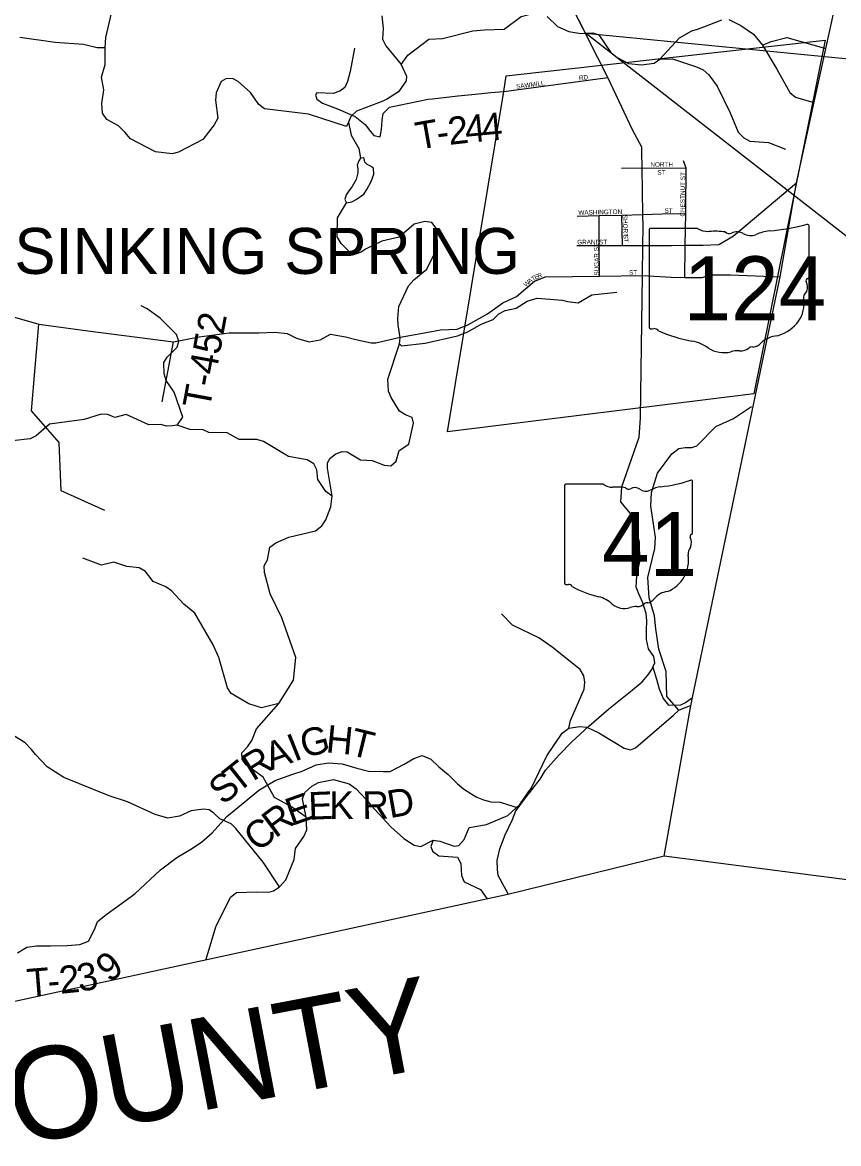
# Model space of a CAD drawing. Extents: x 0 to 34, y 0 to 22.
# Drawn here: x 5.2 to 6.881, y 14.612 to 16.923 of the extents above; entities that cross this region are included whole.
import ezdxf

# ---------------------------------------------------------------- set-up
doc = ezdxf.new("R2010")
doc.units = 0
for name, color, linetype in [('GM_X_Adjacent_County', 7, 'Continuous'), ('GM_X_Adjacent_County_Text', 7, 'Continuous'), ('GM_X_City_Street', 7, 'Continuous'), ('GM_X_City_Street_Text', 7, 'Continuous'), ('GM_X_Corporation', 7, 'Continuous'), ('GM_X_Corporation_Text', 7, 'Continuous'), ('GM_X_County', 7, 'Continuous'), ('GM_X_County_Road', 7, 'Continuous'), ('GM_X_Major_River', 7, 'Continuous'), ('GM_X_Minor_River', 7, 'Continuous'), ('GM_X_State_Location', 7, 'Continuous'), ('GM_X_State_Route', 7, 'Continuous'), ('GM_X_State_Shield', 7, 'Continuous'), ('GM_X_Township_Road', 7, 'Continuous'), ('GM_X_Township_Road_Text', 7, 'Continuous'), ('SH_Data', 7, 'Continuous')]:
    doc.layers.add(name, color=color, linetype=linetype)

msp = doc.modelspace()

# ---------------------------------------------------------------- linework, layer by layer
at = {"layer": 'GM_X_Adjacent_County'}
msp.add_lwpolyline([(9.4, 14.9965), (8.815, 15.0315), (8.2967, 15.0626), (8.1206, 15.0731), (7.1103, 15.1434), (6.9032, 15.1545), (6.5214, 15.204), (6.1992, 15.1249), (5.0219, 14.8699), (4.9843, 14.8636), (3.402, 14.5859), (3.2736, 14.5654), (2.6, 14.46)], dxfattribs=at)
at = {"layer": 'GM_X_City_Street'}
for points in [[(6.1646, 16.7778), (6.1911, 16.7802), (6.4053, 16.8091)], [(6.5648, 16.4601), (6.5648, 16.4632), (6.5658, 16.5289), (6.5659, 16.5373), (6.5666, 16.6223), (6.5609, 16.6375)], [(6.4338, 16.6218), (6.476, 16.6231), (6.5666, 16.6223)], [(6.6341, 16.4651), (6.6344, 16.4652), (6.6354, 16.4652), (6.6643, 16.4826), (6.794, 16.5922)], [(6.3424, 16.5231), (6.3872, 16.5243), (6.4342, 16.5255), (6.4778, 16.5266), (6.5172, 16.5277), (6.5172, 16.5277)], [(6.3879, 16.3996), (6.3875, 16.4627), (6.3872, 16.5243)], [(6.4355, 16.4627), (6.4342, 16.5255)], [(6.5172, 16.5277), (6.5658, 16.5289)], [(6.3415, 16.4628), (6.3875, 16.4627), (6.4355, 16.4627), (6.4778, 16.4628), (6.5368, 16.463), (6.5648, 16.4632), (6.6016, 16.4635), (6.6341, 16.4651)], [(6.5639, 16.3971), (6.5648, 16.4599), (6.5648, 16.4601)], [(6.2173, 16.3576), (6.2543, 16.3895), (6.2771, 16.3981), (6.3879, 16.3996), (6.4771, 16.4008)]]:
    msp.add_lwpolyline(points, dxfattribs=at)
at = {"layer": 'GM_X_Corporation'}
msp.add_lwpolyline([(6.075, 16.0786), (6.1911, 16.7802), (6.1959, 16.8126), (6.8533, 16.8858), (6.7061, 16.157)], close=True, dxfattribs=at)
at = {"layer": 'GM_X_County'}
msp.add_lwpolyline([(6.5214, 15.204), (6.5756, 15.5109), (6.5797, 15.5314), (6.7601, 16.3985), (6.794, 16.5922), (6.9912, 17.4939), (7.1423, 18.303), (7.4503, 19.9984), (7.5281, 20.392), (7.6111, 20.9006)], dxfattribs=at)
at = {"layer": 'GM_X_County_Road'}
msp.add_lwpolyline([(5.1486, 16.3245), (5.2333, 16.3007), (5.3343, 16.2869), (5.511, 16.264), (5.5634, 16.2747), (5.6252, 16.283), (5.6866, 16.2826), (5.7196, 16.2839), (5.745, 16.2811), (5.764, 16.2717), (5.7902, 16.2639), (5.813, 16.2686), (5.8338, 16.2797), (5.8649, 16.2746), (5.8865, 16.269), (5.9177, 16.262), (5.9275, 16.2624), (5.9775, 16.2737), (6.0203, 16.2812), (6.0608, 16.2887), (6.095, 16.29), (6.1169, 16.2993), (6.1573, 16.3219), (6.189, 16.3445), (6.2173, 16.3576)], dxfattribs=at)
at = {"layer": 'GM_X_Major_River'}
for points in [[(5.9401, 16.936), (5.9429, 16.9098), (5.9415, 16.8879), (5.9482, 16.8745), (5.98, 16.8356), (5.9904, 16.8116), (5.9899, 16.8021), (5.9741, 16.7795), (5.9498, 16.7638), (5.9384, 16.759), (5.8879, 16.7394), (5.876, 16.7286), (5.8714, 16.7169), (5.8764, 16.6903), (5.8928, 16.6628), (5.8958, 16.6428)], [(5.8958, 16.6428), (5.8923, 16.6372), (5.8891, 16.6285), (5.8905, 16.6205), (5.8907, 16.6126), (5.8871, 16.599), (5.8789, 16.5843), (5.8719, 16.5757), (5.8661, 16.5675), (5.8636, 16.5577), (5.867, 16.551)], [(5.9051, 16.6343), (5.9035, 16.6423), (5.9011, 16.6432), (5.8958, 16.6428)], [(5.867, 16.551), (5.8779, 16.5525), (5.8867, 16.5573), (5.9028, 16.5687), (5.9087, 16.5785), (5.9177, 16.595), (5.9236, 16.6101), (5.9227, 16.6223), (5.9164, 16.6262), (5.9096, 16.6297), (5.9051, 16.6343)], [(5.7841, 15.2844), (5.7539, 15.3061), (5.7185, 15.3254), (5.6955, 15.3669), (5.6613, 15.3915), (5.6519, 15.4033), (5.6517, 15.417), (5.6631, 15.4294), (5.6724, 15.4429), (5.682, 15.4667), (5.728, 15.5189), (5.7579, 15.5671), (5.7629, 15.6133), (5.7342, 15.6954), (5.7101, 15.7446), (5.6981, 15.789), (5.6974, 15.8027), (5.7044, 15.8151), (5.7092, 15.8408), (5.7214, 15.8498), (5.748, 15.8616), (5.8029, 15.8744), (5.8163, 15.8852), (5.8247, 15.8973), (5.8348, 15.9244), (5.8373, 15.9464), (5.8281, 16.0037), (5.8282, 16.0147), (5.8332, 16.0245), (5.845, 16.0335), (5.8583, 16.0379), (5.8685, 16.0378), (5.8959, 16.0212), (5.9092, 16.02), (5.9198, 16.0198), (5.945, 16.0101), (5.9586, 16.0089), (5.9693, 16.0182), (5.9756, 16.0401), (5.9954, 16.0536), (6.0053, 16.0967), (6.002, 16.1085), (5.9888, 16.1135), (5.9764, 16.1216), (5.9589, 16.1498), (5.9533, 16.1628), (5.9524, 16.1874), (5.9762, 16.2599), (5.9775, 16.2728), (5.9736, 16.2993), (5.9726, 16.3122), (5.9747, 16.3372), (5.9948, 16.3795), (6.0055, 16.3923), (6.0326, 16.414), (6.0508, 16.4517), (6.0521, 16.4759), (6.0516, 16.4983), (6.0426, 16.5101), (6.0283, 16.5125), (6.0066, 16.5067), (5.9754, 16.4797), (5.9397, 16.4714), (5.9078, 16.4561), (5.8971, 16.4487), (5.8876, 16.4453), (5.8752, 16.4477), (5.8564, 16.4669), (5.8479, 16.4806), (5.8486, 16.52), (5.867, 16.551)], [(5.5779, 14.9919), (5.5982, 15.0585), (5.6281, 15.1195), (5.6404, 15.1296), (5.6821, 15.1306), (5.7074, 15.1303), (5.717, 15.1328), (5.7292, 15.141), (5.7422, 15.1552), (5.7595, 15.1975), (5.7617, 15.2202), (5.7794, 15.245), (5.7853, 15.2582), (5.7841, 15.2844)]]:
    msp.add_lwpolyline(points, dxfattribs=at)
at = {"layer": 'GM_X_Minor_River'}
for points in [[(5.98, 16.8356), (5.9931, 16.8548), (6.0369, 16.8877), (6.0645, 16.8893), (6.1275, 16.905), (6.1513, 16.9074), (6.1915, 16.9089), (6.2269, 16.9347), (6.2508, 16.9409), (6.2858, 16.9629), (6.309, 16.9725), (6.3319, 16.9901), (6.3544, 17.0138), (6.4018, 17.0243), (6.4383, 17.0395), (6.46, 17.0529), (6.4964, 17.0578), (6.507, 17.0642), (6.5207, 17.0724), (6.5302, 17.078), (6.573, 17.1219), (6.593, 17.146), (6.6179, 17.1844), (6.6305, 17.196)], [(5.8714, 16.7169), (5.8671, 16.7078), (5.7891, 16.7336), (5.698, 16.7444), (5.6864, 16.7536), (5.6692, 16.7784), (5.6437, 16.8006), (5.632, 16.8068), (5.6184, 16.8062), (5.6089, 16.8006), (5.5984, 16.7772), (5.5972, 16.7624), (5.6017, 16.7252), (5.5948, 16.7113), (5.5714, 16.6812), (5.5212, 16.6548), (5.5079, 16.6515), (5.4735, 16.6556), (5.422, 16.6827), (5.4104, 16.6964), (5.3972, 16.7091), (5.3735, 16.7222), (5.3646, 16.7352), (5.3629, 16.7556), (5.3673, 16.7833), (5.3623, 16.8098), (5.3701, 16.8355), (5.3701, 16.87), (5.3714, 16.8912), (5.3829, 16.9415)], [(6.2806, 16.9349), (6.3016, 16.9138), (6.3253, 16.9041), (6.3495, 16.8997), (6.3745, 16.9014), (6.3866, 16.8967), (6.4116, 16.8608), (6.4243, 16.8505), (6.4477, 16.8381), (6.4745, 16.8348), (6.501, 16.8387), (6.5128, 16.8469), (6.553, 16.8909), (6.5781, 16.9054), (6.5899, 16.9087), (6.6031, 16.9135), (6.6404, 16.9279)], [(6.6544, 16.9282), (6.6792, 16.9162), (6.7055, 16.8985), (6.7242, 16.8755), (6.7532, 16.826), (6.78, 16.778), (6.7916, 16.7684), (6.8298, 16.7576)], [(6.7242, 16.8755), (6.7417, 16.8833), (6.7739, 16.8917), (6.8542, 16.8685)], [(5.3701, 16.87), (5.3538, 16.8702), (5.3255, 16.8773), (5.2669, 16.8809), (5.194, 16.8911)], [(6.5128, 16.8469), (6.5389, 16.8474), (6.5883, 16.831), (6.6015, 16.8248), (6.6135, 16.8145), (6.6307, 16.7912), (6.6574, 16.736), (6.6736, 16.696), (6.6853, 16.6845), (6.6981, 16.678), (6.7362, 16.6753), (6.7713, 16.6613)], [(5.9762, 16.2599), (5.9807, 16.2557), (6.0288, 16.2617), (6.0956, 16.2769), (6.1172, 16.285), (6.1446, 16.3007), (6.1689, 16.3103), (6.1811, 16.3219), (6.1937, 16.329), (6.2164, 16.3333), (6.2393, 16.3479), (6.2598, 16.3541), (6.3123, 16.3502), (6.3225, 16.347), (6.3444, 16.3449), (6.3722, 16.361), (6.4237, 16.3665)], [(5.5183, 16.0928), (5.5298, 16.109), (5.5118, 16.1603), (5.4954, 16.1847), (5.4913, 16.1984), (5.4908, 16.2215), (5.4974, 16.2328), (5.5184, 16.2535), (5.5215, 16.2659), (5.5167, 16.2793), (5.483, 16.3129), (5.4563, 16.3325), (5.4439, 16.3383)], [(6.5515, 15.5054), (6.5272, 15.533), (6.5252, 15.5849), (6.5103, 15.631), (6.504, 15.6728), (6.5014, 15.6998), (6.4905, 15.7367), (6.488, 15.7788), (6.5024, 15.8382), (6.5038, 15.8617), (6.4941, 15.9255), (6.4952, 15.9539), (6.5078, 15.9932), (6.5371, 16.0334), (6.5513, 16.0442), (6.5646, 16.0467), (6.5782, 16.0465), (6.5885, 16.0498), (6.628, 16.0898), (6.6642, 16.1064), (6.7014, 16.1306)], [(5.8373, 15.9464), (5.8242, 15.956), (5.8082, 15.9808), (5.8057, 16.0001), (5.8001, 16.0131), (5.7862, 16.0212), (5.7473, 16.0276), (5.6962, 16.0588), (5.6826, 16.0631), (5.6463, 16.0631), (5.6211, 16.0766), (5.5836, 16.0774), (5.5716, 16.0828), (5.5443, 16.0834), (5.5183, 16.0928), (5.5088, 16.0914), (5.4963, 16.0907), (5.4846, 16.0935), (5.46, 16.0934), (5.4133, 16.1143), (5.3898, 16.1081), (5.3755, 16.1143), (5.3619, 16.1152), (5.3266, 16.1042), (5.255, 16.0943), (5.2279, 16.0707), (5.2153, 16.064), (5.179, 16.0602)], [(5.728, 15.5189), (5.6919, 15.5102), (5.6659, 15.518), (5.6294, 15.5396), (5.622, 15.5514), (5.6044, 15.6137), (5.5926, 15.64), (5.555, 15.7048), (5.5321, 15.7236), (5.5066, 15.7511), (5.4946, 15.7596), (5.469, 15.7701), (5.4529, 15.7907), (5.4401, 15.7984), (5.4144, 15.8009), (5.3877, 15.8099), (5.3622, 15.8041), (5.3242, 15.8181)], [(6.3248, 15.4681), (6.3284, 15.484), (6.3566, 15.5481), (6.3583, 15.5629), (6.3562, 15.5758), (6.3484, 15.5888), (6.2906, 15.635), (6.2632, 15.654), (6.209, 15.6804), (6.1862, 15.7039)], [(5.7841, 15.2844), (5.7766, 15.322), (5.781, 15.3356), (5.7955, 15.3487), (5.8096, 15.3561), (5.8404, 15.3625), (5.8729, 15.353), (5.8868, 15.343), (5.9069, 15.3215), (5.9178, 15.3088), (5.9581, 15.2647), (5.9851, 15.2404), (6.0065, 15.2269), (6.0201, 15.2244), (6.0456, 15.237), (6.0596, 15.2353), (6.0887, 15.2251), (6.0985, 15.2264), (6.1093, 15.2388), (6.1199, 15.2633), (6.1556, 15.2697), (6.1997, 15.2881), (6.2239, 15.3105), (6.2409, 15.335), (6.2482, 15.3447), (6.2794, 15.4111), (6.3111, 15.458), (6.3248, 15.4681), (6.3476, 15.4716), (6.3624, 15.4699), (6.3868, 15.4586), (6.4387, 15.4268), (6.4523, 15.4236), (6.4622, 15.4273), (6.5407, 15.4945), (6.5515, 15.5054), (6.5771, 15.5153)], [(5.7292, 15.141), (5.6954, 15.1919), (5.6391, 15.2612), (5.6293, 15.2705), (5.6064, 15.2814), (5.594, 15.2929), (5.5843, 15.2999), (5.5725, 15.3011), (5.5471, 15.2973), (5.5231, 15.2866), (5.4992, 15.2828), (5.4731, 15.2903), (5.4163, 15.3164), (5.3782, 15.3287), (5.2847, 15.3663), (5.2505, 15.388), (5.2266, 15.4137), (5.2184, 15.4237), (5.2053, 15.4375), (5.1801, 15.4534)], [(6.0456, 15.237), (6.0409, 15.2242), (6.0442, 15.2146), (6.0573, 15.205), (6.0956, 15.2022), (6.1026, 15.1888), (6.1038, 15.1642), (6.1097, 15.1516), (6.1432, 15.1356), (6.1562, 15.1169)]]:
    msp.add_lwpolyline(points, dxfattribs=at)
at = {"layer": 'GM_X_State_Route'}
for points in [[(6.385, 16.8494), (6.2653, 17.0868), (6.2581, 17.1154), (6.2538, 17.1382), (6.2585, 17.3365), (6.2591, 17.3607)], [(6.3593, 16.9004), (6.319, 16.9802)], [(6.4754, 16.656), (6.4753, 16.6651), (6.4564, 16.701), (6.4053, 16.8091), (6.3851, 16.8493), (6.385, 16.8494)], [(6.4729, 16.1086), (6.4729, 16.1088), (6.4771, 16.4008), (6.4778, 16.4628), (6.4783, 16.501), (6.4778, 16.5266), (6.476, 16.6231), (6.4754, 16.6559), (6.4754, 16.656)], [(6.4771, 16.4008), (6.5355, 16.3974), (6.5639, 16.3971), (6.5996, 16.3966), (6.6168, 16.4025), (6.6581, 16.4023), (6.7601, 16.3985)], [(6.2005, 15.1252), (6.1793, 15.1642), (6.1783, 15.1764), (6.1777, 15.195), (6.183, 15.2196), (6.1939, 15.248), (6.2087, 15.2797), (6.2161, 15.2978), (6.2206, 15.304), (6.2315, 15.3189), (6.2657, 15.3629), (6.2773, 15.3817), (6.305, 15.4133), (6.331, 15.4399), (6.3659, 15.4721), (6.4076, 15.5081), (6.4524, 15.5436), (6.4761, 15.5638), (6.488, 15.5769), (6.4957, 15.5886), (6.4979, 15.5934), (6.5023, 15.6029), (6.4998, 15.6155), (6.4894, 15.6312), (6.4851, 15.6506), (6.4849, 15.6703), (6.4859, 15.6889), (6.4846, 15.7041), (6.4776, 15.7266), (6.4691, 15.7446), (6.4636, 15.7583), (6.465, 15.7818), (6.4714, 15.8117), (6.4704, 15.852), (6.4635, 15.8786), (6.4614, 15.8935), (6.4551, 15.9072), (6.4442, 15.9191), (6.4319, 15.9344), (6.4345, 15.9655), (6.4702, 16.0676), (6.4729, 16.1078), (6.4729, 16.1086)]]:
    msp.add_lwpolyline(points, dxfattribs=at)
at = {"layer": 'GM_X_State_Shield'}
for p, q in [((6.8198, 16.3983), (6.8198, 16.503)), ((6.4902, 16.4946), (6.4902, 16.2945)), ((6.59, 16.4981), (6.4935, 16.4981)), ((6.8198, 16.3984), (6.8198, 16.3983)), ((6.3163, 15.9675), (6.3163, 15.7674)), ((6.3961, 15.971), (6.3189, 15.971)), ((6.5799, 15.8712), (6.5799, 15.9759)), ((6.5799, 15.8713), (6.5799, 15.8712))]:
    msp.add_line(p, q, dxfattribs=at)
for centre, radius, start, end in [((6.3193, 15.968), 0.00305, 98.1301, 188.1301), ((6.4145, 15.9942), 0.0296, 231.6195, 271.1119), ((6.486, 16.2438), 0.2796, 275.8445, 288.9065), ((6.577, 15.9764), 0.00294, 351.8621, 97.738), ((6.4243, 15.8586), 0.1064, 80.4867, 94.9883), ((6.4484, 15.969), 0.00855, 219.7921, 297.1024), ((6.461, 15.9459), 0.0178, 54.4667, 119.1411), ((6.4839, 15.9776), 0.0214, 233.8562, 294.8282), ((6.5217, 15.9098), 0.0563, 97.3462, 120.7689), ((6.5792, 15.8636), 0.00454, 107.944, 210.337), ((6.5503, 15.8503), 0.0273, 340.033, 23.6496), ((6.5768, 15.8708), 0.00314, 289.6038, 7.7341), ((6.5904, 15.8274), 0.0198, 136.8065, 186.9296), ((6.5017, 15.8141), 0.0699, 292.3089, 8.9858), ((6.3193, 15.767), 0.00308, 171.9584, 258.3066), ((6.3198, 15.7874), 0.0235, 267.339, 280.6039), ((6.3246, 15.7559), 0.00848, 29.7484, 93.2717), ((6.4316, 15.9357), 0.2019, 240.4129, 257.1985), ((6.3714, 15.6775), 0.0632, 47.1842, 75.836), ((6.5312, 15.7112), 0.0383, 94.4031, 142.5768), ((6.4398, 15.7549), 0.0401, 230.7004, 286.2918), ((6.4629, 15.6857), 0.0329, 85.6951, 111.2099), ((6.4659, 15.7399), 0.0214, 268.777, 315.5493), ((6.4852, 15.7205), 0.00601, 65.7517, 132.6484), ((6.4826, 15.748), 0.0226, 282.8732, 323.2771)]:
    msp.add_arc(centre, radius, start, end, dxfattribs=at)
for centre, major_axis, start_param, end_param in [((6.7024, 16.7709), (0.3495, 0), 4.814394, 5.042369), ((6.8162, 16.5034), (0.00367, 0), 6.141152, 7.989035), ((6.494, 16.495), (0.00382, 0), 1.712693, 3.28349), ((6.613, 16.5213), (0.037, 0), 4.042523, 4.731795), ((6.6253, 16.3857), (0.133, 0), 1.404758, 1.657858), ((6.6555, 16.4961), (0.0107, 0), 3.836095, 5.185415), ((6.6711, 16.4729), (0.0222, 0), 0.950623, 2.079405), ((6.6998, 16.5047), (0.0267, 0), 4.081561, 5.145723), ((6.747, 16.4369), (0.0703, 0), 1.699011, 2.107814), ((6.819, 16.3906), (0.00568, 0), 1.883978, 3.671073), ((6.7829, 16.3774), (0.0341, 0), 5.934695, 6.695948), ((6.8159, 16.3979), (0.00393, 0), 5.05454, 6.418171), ((6.833, 16.3545), (0.0248, 0), 2.387724, 3.262537), ((6.722, 16.3412), (0.0874, 0), 5.101752, 6.440018), ((6.4941, 16.2941), (0.00385, 0), 3.00124, 4.508301), ((6.4946, 16.3145), (0.0294, 0), 4.665946, 4.897461), ((6.5007, 16.2829), (0.0106, 0), 0.519207, 1.627899), ((6.6345, 16.4627), (0.2524, 0), 4.195997, 4.488961), ((6.7589, 16.2383), (0.0479, 0), 1.647645, 2.488434), ((6.5592, 16.2046), (0.079, 0), 0.823519, 1.323587), ((6.6446, 16.282), (0.0501, 0), 4.026481, 4.996735), ((6.6736, 16.2128), (0.0412, 0), 1.495662, 1.94098), ((6.6773, 16.267), (0.0267, 0), 4.691044, 5.507374), ((6.7014, 16.2476), (0.00752, 0), 1.147584, 2.315152), ((6.6982, 16.2751), (0.0282, 0), 4.937069, 5.64225)]:
    msp.add_ellipse(centre, major_axis=major_axis, ratio=0.8, start_param=start_param, end_param=end_param, dxfattribs=at)
at = {"layer": 'GM_X_Township_Road'}
for points in [[(5.8837, 16.8695), (5.8745, 16.8211), (5.8693, 16.8008), (5.8633, 16.7885), (5.8533, 16.781), (5.8394, 16.7758), (5.8057, 16.7774), (5.8031, 16.7728), (5.8063, 16.7646), (5.8178, 16.7559), (5.8485, 16.7447), (5.8851, 16.7286), (5.9053, 16.7124), (5.9163, 16.6977), (5.9232, 16.6894), (5.9365, 16.6864), (5.9395, 16.7016), (5.9408, 16.7214), (5.9427, 16.735), (5.9555, 16.7476), (6.0354, 16.7641), (6.0439, 16.765)], [(6.0439, 16.765), (6.0961, 16.7711), (6.0971, 16.7713), (6.1456, 16.7761), (6.1646, 16.7778)], [(5.3693, 15.9164), (5.2792, 15.9572), (5.2755, 16.0566), (5.2182, 16.1223), (5.2333, 16.3007)], [(5.4877, 16.1403), (5.511, 16.264)], [(6.4979, 15.5934), (6.5058, 15.5693), (6.5109, 15.5492), (6.5194, 15.5288), (6.5301, 15.5155), (6.5555, 15.5159), (6.5652, 15.5209), (6.5797, 15.5314)], [(5.1891, 15.0049), (5.2087, 15.0164), (5.2284, 15.0196), (5.2576, 15.0194), (5.2914, 15.0203), (5.3179, 15.022), (5.3353, 15.029), (5.3484, 15.0541), (5.3544, 15.0697), (5.374, 15.0854), (5.4038, 15.1068), (5.431, 15.1267), (5.4841, 15.176), (5.5173, 15.2016), (5.5464, 15.2189), (5.5683, 15.2327), (5.5902, 15.2521), (5.6207, 15.2861), (5.658, 15.3167), (5.6863, 15.34), (5.7199, 15.3603), (5.7566, 15.3735), (5.7756, 15.3796), (5.8043, 15.3923), (5.8301, 15.3967), (5.8581, 15.3942), (5.8881, 15.3856), (5.9125, 15.3797), (5.9428, 15.3788), (5.9572, 15.3789), (5.9859, 15.3938), (6.0056, 15.4053), (6.023, 15.4119), (6.0405, 15.4044), (6.0576, 15.3882), (6.0763, 15.3727), (6.0958, 15.3535), (6.108, 15.343), (6.1251, 15.3321), (6.1358, 15.3261), (6.1495, 15.3201), (6.1643, 15.3164), (6.1836, 15.3157), (6.2206, 15.304)]]:
    msp.add_lwpolyline(points, dxfattribs=at)
at = {"layer": 'SH_Data'}
msp.add_lwpolyline([(6.3593, 16.9004), (7.373, 16.8016), (7.373, 16.111)], close=True, dxfattribs=at)

# ---------------------------------------------------------------- texts
at = {"layer": 'GM_X_Adjacent_County_Text'}
msp.add_text('ADAMS COUNTY', height=0.189394, rotation=10.7426, dxfattribs=at).set_placement((4.054, 14.3918))
at = {"layer": 'GM_X_City_Street_Text'}
for s, rotation, p in [('SAWMILL', 7.128, (6.2171, 16.7858)), ('RD', 6.0054, (6.3463, 16.8033)), ('NORTH', 0, (6.4931, 16.625)), ('ST', 0, (6.5073, 16.6087)), ('CHESTNUT ST', 89.3781, (6.5639, 16.5224)), ('WASHINGTON', 1.2182, (6.3448, 16.5259)), ('SHORT', 272.5433, (6.4358, 16.5258)), ('ST', 0, (6.5223, 16.53)), ('ST', 273.5874, (6.4374, 16.485)), ('GRAND', 0, (6.3423, 16.465)), ('SUGAR ST', 90.8546, (6.3872, 16.4007)), ('ST', 0, (6.3873, 16.465)), ('ST', 0, (6.449, 16.4025)), ('W', 42.1335, (6.2368, 16.3768)), ('A', 38.3262, (6.2447, 16.384)), ('T', 30.7115, (6.251, 16.3889)), ('E', 23.0969, (6.2564, 16.3922)), ('R', 19.2896, (6.2624, 16.3948))]:
    msp.add_text(s, height=0.00947, rotation=rotation, dxfattribs=at).set_placement(p)
at = {"layer": 'GM_X_Corporation_Text'}
msp.add_text('SINKING SPRING', height=0.094697, rotation=0, dxfattribs=at).set_placement((5.1831, 16.4042))
at = {"layer": 'GM_X_State_Location'}
msp.add_text('124', height=0.000189, rotation=0, dxfattribs=at).set_placement((6.5515, 16.366))
for s in ['s', 'r']:
    msp.add_text(s, height=0.000189, dxfattribs=at).set_placement((6.6183, 16.3798))
at = {"layer": 'GM_X_State_Shield'}
for s, p in [('124', (6.5613, 16.3086)), ('41', (6.3934, 15.7815))]:
    msp.add_text(s, height=0.13184, dxfattribs=at).set_placement(p)
at = {"layer": 'GM_X_Township_Road_Text'}
for s, height, rotation, p in [('2', 0.0568, 6.3827, (6.0789, 16.67)), ('4', 0.0568, 5.504, (6.1134, 16.6739)), ('4', 0.0568, 5.2684, (6.1482, 16.6772)), ('T', 0.0568, 10.0936, (6.0148, 16.6597)), ('-', 0.0568, 7.3739, (6.056, 16.667)), ('T-452', 0.05682, 79.5701, (5.5851, 16.1237)), ('G', 0.0568, 14.1343, (5.7798, 15.4064)), ('H', 0.0568, 354.4435, (5.8232, 15.4183)), ('T', 0.0568, 346.1997, (5.8708, 15.4138)), ('A', 0.0568, 19.9327, (5.7112, 15.3806)), ('I', 0.0568, 21.8598, (5.7601, 15.3984)), ('R', 0.0568, 31.283, (5.674, 15.3576)), ('T', 0.0568, 38.5681, (5.6423, 15.3322)), ('S', 0.0568, 39.6942, (5.613, 15.3079)), ('D', 0.0568, 10.0172, (5.9565, 15.2823)), ('E', 0.0568, 19.4379, (5.7538, 15.2659)), ('E', 0.0568, 2.2377, (5.7895, 15.2792)), ('K', 0.0568, 359.8616, (5.8313, 15.2809)), ('R', 0.0568, 0.8272, (5.9, 15.2807)), ('R', 0.0568, 36.8059, (5.7205, 15.2401)), ('C', 0.0568, 39.2334, (5.6848, 15.211)), ('9', 0.0568, 37.2042, (5.3785, 14.942)), ('T', 0.0568, 4.5818, (5.211, 14.9149)), ('2', 0.0568, 5.7138, (5.2778, 14.9204)), ('3', 0.0568, 9.5822, (5.3168, 14.9244)), ('-', 0.0568, 4.7928, (5.2536, 14.9184))]:
    msp.add_text(s, height=height, rotation=rotation, dxfattribs=at).set_placement(p)

doc.saveas('drawing.dxf')
